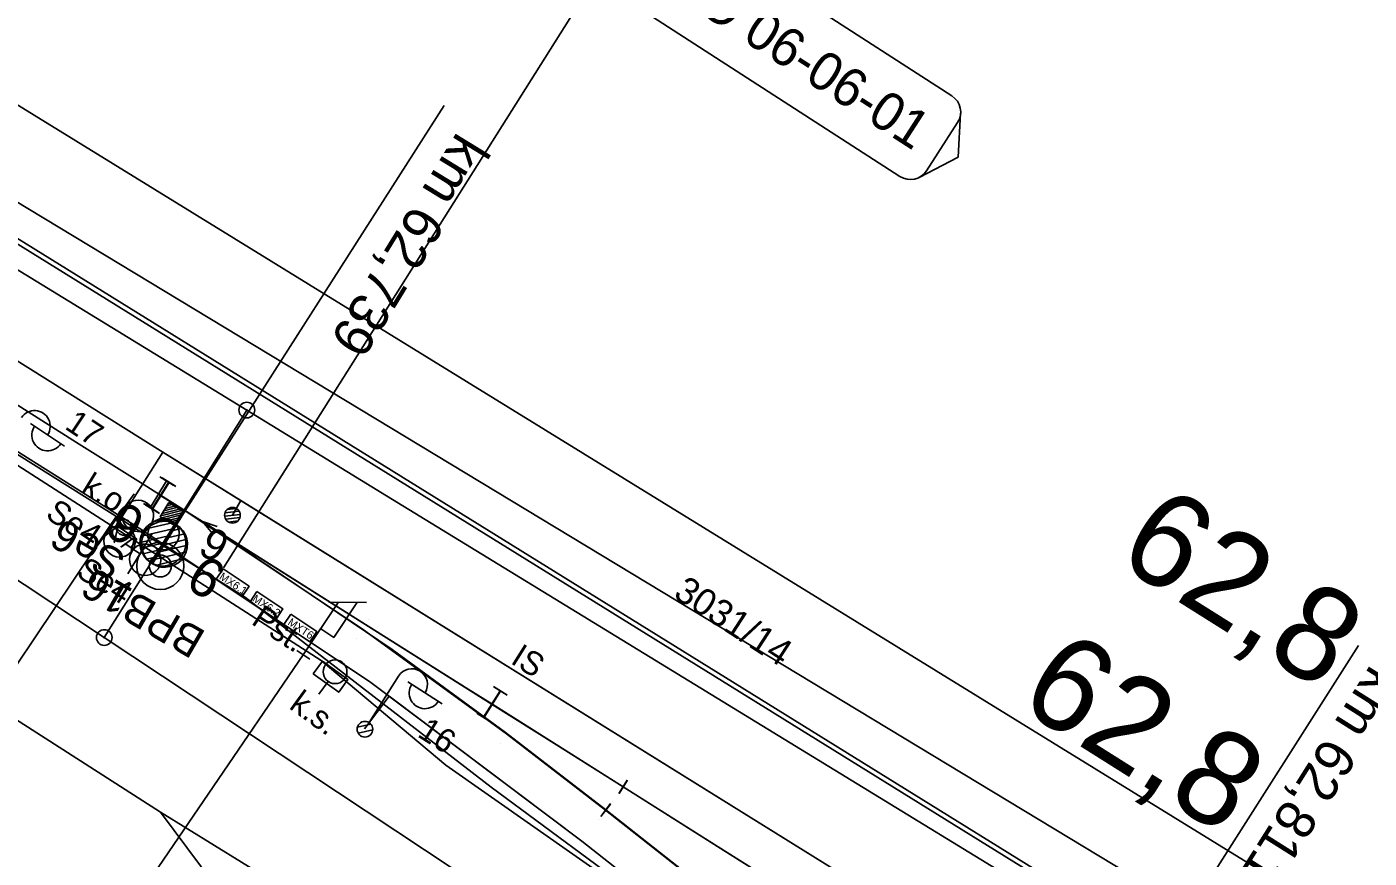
# Model space of a CAD drawing. Extents: x -621168 to -620292, y -1122748 to -1122069.
# Drawn here: x -620861.7 to -620776.3, y -1122349.2 to -1122296.3 of the extents above; entities that cross this region are included whole.
import ezdxf

# ---------------------------------------------------------------- set-up
doc = ezdxf.new("R2010")
doc.units = 0
for name, color, linetype in [('060601_EOV', 7, 'Continuous'), ('060604_ROZVODY_SEE', 7, 'Continuous'), ('bubliny', 7, 'Continuous'), ('CETIN', 7, 'Continuous'), ('HranDP', 7, 'Continuous'), ('Hranice parcel', 7, 'Continuous'), ('Parcelní čísla', 7, 'Continuous'), ('PS 06-14-01_trasa_sdělovací_nové', 7, 'Continuous'), ('SEE', 7, 'Continuous'), ('SSZT', 7, 'Continuous'), ('SSZT-DK', 7, 'Continuous'), ('UZEMNĚNÍ', 7, 'Continuous'), ('Vrstva 1', 7, 'Continuous'), ('Vrstva 10', 7, 'Continuous'), ('Vrstva 2', 7, 'Continuous'), ('Vrstva 25', 7, 'Continuous'), ('Vrstva 27', 7, 'Continuous'), ('Vrstva 3', 7, 'Continuous'), ('Vrstva 36', 7, 'Continuous'), ('Vrstva 6', 7, 'Continuous'), ('Vrstva 62', 7, 'Continuous'), ('Vrstva 7', 7, 'Continuous'), ('Značky bodu BP', 7, 'Continuous'), ('ČD-T', 7, 'Continuous')]:
    doc.layers.add(name, color=color, linetype=linetype)

msp = doc.modelspace()

# ---------------------------------------------------------------- linework, layer by layer
at = {"layer": '060601_EOV'}
msp.add_line((-620846.682, -1122333.419), (-620846.69, -1122333.431), dxfattribs=at)
for points in [[(-620849.226, -1122330.78), (-620847.572, -1122331.882), (-620848.007, -1122332.536), (-620849.661, -1122331.435)], [(-620847.074, -1122332.214), (-620845.42, -1122333.316), (-620845.855, -1122333.97), (-620847.509, -1122332.868)], [(-620844.922, -1122333.647), (-620843.268, -1122334.749), (-620843.703, -1122335.403), (-620845.357, -1122334.302)]]:
    msp.add_lwpolyline(points, close=True, dxfattribs=at)
for points in [[(-620377.179, -1122637.257), (-620411.557, -1122614.916), (-620424.156, -1122607.087), (-620443.525, -1122595.005), (-620456.111, -1122587.123), (-620447.823, -1122572.959), (-620450.948, -1122571.455), (-620470.592, -1122561.479), (-620499.61, -1122545.574), (-620522.038, -1122531.471), (-620538.89, -1122521.208), (-620599.215, -1122483.216), (-620683.524, -1122429.444), (-620729.121, -1122400.659), (-620738.886, -1122415.694), (-620750.529, -1122408.246), (-620763.558, -1122399.82), (-620784.65, -1122386.386), (-620822.218, -1122362.419), (-620817.53, -1122355.085), (-620826.407, -1122348.082), (-620839.916, -1122337.943), (-620848.842, -1122331.997), (-620848.834, -1122331.986)], [(-620844.53, -1122334.853), (-620844.531, -1122334.852), (-620844.539, -1122334.864)]]:
    msp.add_lwpolyline(points, dxfattribs=at)
at = {"layer": '060604_ROZVODY_SEE'}
msp.add_line((-620840.227, -1122340.951), (-620838.671, -1122338.878), dxfattribs=at)
msp.add_lwpolyline([(-620443.525, -1122595.005), (-620456.111, -1122587.123), (-620447.823, -1122572.959), (-620450.948, -1122571.455), (-620470.592, -1122561.479), (-620499.61, -1122545.574), (-620522.038, -1122531.471), (-620538.89, -1122521.208), (-620599.215, -1122483.216), (-620683.524, -1122429.444), (-620729.121, -1122400.659), (-620738.886, -1122415.694), (-620750.529, -1122408.246), (-620763.558, -1122399.82), (-620784.65, -1122386.386), (-620822.218, -1122362.419), (-620817.53, -1122355.085), (-620826.407, -1122348.082), (-620839.916, -1122337.943), (-620854.567, -1122328.184), (-620868.06, -1122319.694), (-620885.37, -1122308.815), (-620912.868, -1122291.527), (-620913.325, -1122292.255)], dxfattribs=at)
at = {"layer": 'bubliny'}
msp.add_line((-620849.204, -1122330.707), (-620823.975, -1122290.686), dxfattribs=at)
for points in [[(-620821.297, -1122288.788), (-620802.862, -1122300.695)], [(-620806.17, -1122305.815), (-620824.604, -1122293.908)], [(-620802.307, -1122301.789), (-620802.468, -1122304.578), (-620804.944, -1122305.872)], [(-620804.484, -1122305.453), (-620802.5, -1122302.38)], [(-620802.5, -1122302.38), (-620804.484, -1122305.453)]]:
    msp.add_lwpolyline(points, dxfattribs=at)
for centre, start, end in [((-620803.524, -1122301.719), 327.14101, 57.14101), ((-620803.524, -1122301.719), 327.14101, 356.69293), ((-620805.508, -1122304.791), 237.14101, 327.14101), ((-620805.508, -1122304.791), 297.58925, 327.14101)]:
    msp.add_arc(centre, 1.219, start, end, dxfattribs=at)
at = {"layer": 'CETIN'}
msp.add_lwpolyline([(-621086.886, -1122186.715), (-621044.703, -1122204.841), (-620975.938, -1122239.692), (-620943.103, -1122258.616), (-620748.436, -1122376.269), (-620484.52, -1122538.147)], dxfattribs=at)
at = {"layer": 'HranDP'}
msp.add_line((-620856.79, -1122335.14), (-620821.12, -1122358.76), dxfattribs=at)
for points in [[(-620847.72, -1122320.67), (-620907.48, -1122284.08), (-620974.87, -1122244.96), (-620982.44, -1122240.65)], [(-620902.62, -1122306.44), (-620882.26, -1122318.28), (-620856.79, -1122335.14)], [(-620847.72, -1122320.67), (-620838.83, -1122326.12), (-620768.63, -1122369.09), (-620748.53, -1122378.52), (-620702.13, -1122406.7), (-620691.02, -1122413.66), (-620638.48, -1122446.57), (-620552.09, -1122499.2)]]:
    msp.add_lwpolyline(points, dxfattribs=at)
at = {"layer": 'Hranice parcel'}
for p, q in [((-620866.03, -1122298.98), (-620688.16, -1122408.5)), ((-620853.22, -1122346.25), (-620894.54, -1122319.77)), ((-620847.72, -1122320.67), (-620856.79, -1122335.14)), ((-620856.79, -1122335.14), (-620821.12, -1122358.76))]:
    msp.add_line(p, q, dxfattribs=at)
for points in [[(-620847.72, -1122320.67), (-620907.48, -1122284.08), (-620974.87, -1122244.96), (-620982.44, -1122240.65)], [(-620902.62, -1122306.44), (-620882.26, -1122318.28), (-620856.79, -1122335.14)], [(-620847.72, -1122320.67), (-620838.83, -1122326.12), (-620768.63, -1122369.09), (-620748.53, -1122378.52), (-620702.13, -1122406.7), (-620691.02, -1122413.66), (-620638.48, -1122446.57), (-620552.09, -1122499.2)], [(-620825.92, -1122365.89), (-620834.44, -1122358.28), (-620836.04, -1122356.85), (-620853.22, -1122346.25)], [(-620853.22, -1122346.25), (-620843.09, -1122359.81), (-620845.8, -1122363.88), (-620848.5, -1122367.99), (-620848.87, -1122368.55)]]:
    msp.add_lwpolyline(points, dxfattribs=at)
at = {"layer": 'PS 06-14-01_trasa_sdělovací_nové'}
msp.add_lwpolyline([(-620756.33, -1122383.523), (-620759.752, -1122381.362), (-620756.353, -1122375.206), (-620764.724, -1122371.2), (-620767.847, -1122376.3), (-620853.066, -1122323.342), (-620895.691, -1122296.632), (-620912.11, -1122286.226), (-620914.885, -1122290.617), (-620964.537, -1122259.534), (-620982.106, -1122249.221), (-620983.24, -1122251.5), (-621017.63, -1122231.729), (-621052.339, -1122216.079), (-621085.519, -1122202.489), (-621084.026, -1122198.756), (-621092.027, -1122195.557)], dxfattribs=at)
at = {"layer": 'SEE'}
msp.add_lwpolyline([(-620377.188, -1122637.273), (-620390.254, -1122629.02), (-620411.934, -1122614.961), (-620423.125, -1122608.012), (-620468.337, -1122579.91), (-620468.337, -1122579.91), (-620460.94, -1122568.103), (-620517.418, -1122533.032), (-620535.001, -1122522.477), (-620545.407, -1122539.454), (-620611.375, -1122497.696), (-620665.569, -1122462.755), (-620686.035, -1122449.829), (-620727.537, -1122423.183), (-620794.508, -1122379.862), (-620815.52, -1122356.954), (-620832.168, -1122344.663), (-620847.808, -1122332.592), (-620908.257, -1122294.686)], dxfattribs=at)
at = {"layer": 'SSZT'}
msp.add_lwpolyline([(-620879.238, -1122313.316), (-620842.993, -1122336.61), (-620835.049, -1122343.251), (-620812.66, -1122358.949), (-620764.902, -1122389.752), (-620688.594, -1122438.969), (-620596.981, -1122496.725), (-620576.744, -1122509.484), (-620506.746, -1122556.123), (-620447.293, -1122593.619), (-620377.761, -1122638.259)], dxfattribs=at)
at = {"layer": 'SSZT-DK'}
msp.add_lwpolyline([(-621084.334, -1122182.327), (-621080.248, -1122184.036), (-621051.504, -1122198.928), (-620999.37, -1122227.003), (-620959.935, -1122250.539), (-620931.349, -1122267.519), (-620900.269, -1122286.467), (-620889.147, -1122293.455), (-620783.743, -1122358.818), (-620712.751, -1122398.176), (-620653.117, -1122435.232), (-620617.363, -1122456.738), (-620574.425, -1122482.604), (-620528.157, -1122511.106), (-620496.311, -1122530.834), (-620515.025, -1122558.813), (-620500.383, -1122568.606), (-620465.393, -1122591.454), (-620452.16, -1122605.021), (-620438.234, -1122615.496), (-620392.309, -1122655.212), (-620389.253, -1122658.022)], dxfattribs=at)
at = {"layer": 'UZEMNĚNÍ'}
msp.add_lwpolyline([(-620742.353, -1122414.851), (-620741.729, -1122413.876), (-620750.529, -1122408.246), (-620763.558, -1122399.82), (-620784.65, -1122386.386), (-620822.218, -1122362.419), (-620817.53, -1122355.085), (-620826.407, -1122348.082), (-620838.671, -1122338.878), (-620840.227, -1122340.951)], dxfattribs=at)
at = {"layer": 'Vrstva 1'}
for p, q in [((-620856.015, -1122328.01), (-620853.066, -1122323.342)), ((-620848.094, -1122326.432), (-620853.066, -1122323.342)), ((-620806.105, -1122352.525), (-620848.094, -1122326.432)), ((-620856.015, -1122328.01), (-620854.725, -1122328.89))]:
    msp.add_line(p, q, dxfattribs=at)
for points in [[(-620853.066, -1122323.342), (-620895.691, -1122296.632), (-620912.11, -1122286.226)], [(-620865.133, -1122318.582), (-620858.377, -1122322.838), (-620854.485, -1122325.283), (-620853.208, -1122326.085), (-620851.733, -1122327.008), (-620850.549, -1122327.758), (-620840.578, -1122334.049), (-620833.632, -1122338.433), (-620832.14, -1122339.366), (-620823.776, -1122344.632), (-620817.743, -1122348.457), (-620811.366, -1122352.452)], [(-620853.345, -1122326.031), (-620853.187, -1122326.13), (-620851.644, -1122327.076), (-620843.142, -1122332.434), (-620837.627, -1122335.918), (-620832.116, -1122339.39), (-620828.016, -1122341.966), (-620823.788, -1122344.633), (-620816.971, -1122348.943), (-620810.355, -1122353.089), (-620803.86, -1122357.181), (-620803.36, -1122357.495), (-620800.131, -1122359.525), (-620798.65, -1122360.458), (-620794.421, -1122363.123), (-620788.102, -1122367.105), (-620781.123, -1122371.499), (-620774.168, -1122375.876)], [(-620848.094, -1122326.432), (-620848.094, -1122326.432), (-620848.634, -1122327.362)], [(-620851.644, -1122327.076), (-620843.142, -1122332.434), (-620837.627, -1122335.918), (-620832.116, -1122339.39), (-620828.016, -1122341.966), (-620823.788, -1122344.633), (-620816.971, -1122348.943), (-620810.355, -1122353.089), (-620803.86, -1122357.181), (-620803.36, -1122357.495), (-620800.131, -1122359.525), (-620798.65, -1122360.458), (-620794.421, -1122363.123), (-620788.102, -1122367.105), (-620781.123, -1122371.499), (-620774.168, -1122375.876), (-620767.514, -1122380.058), (-620763.223, -1122382.761), (-620756.392, -1122387.049), (-620748.87, -1122391.776), (-620741.59, -1122396.353), (-620734.607, -1122400.749), (-620727.792, -1122405.031)], [(-620851.644, -1122327.076), (-620840.376, -1122334.591), (-620831.192, -1122341.263), (-620824.896, -1122346.12), (-620811.348, -1122356.777), (-620800.849, -1122364.554), (-620800.095, -1122365.072), (-620796.174, -1122367.693), (-620795.017, -1122368.443), (-620786.31, -1122373.928), (-620764.415, -1122387.671), (-620747.632, -1122398.188), (-620733.731, -1122406.893), (-620718.349, -1122416.524), (-620703.006, -1122426.145), (-620686.977, -1122436.203), (-620670.849, -1122446.339), (-620652.243, -1122458.025), (-620632.992, -1122470.125), (-620616.992, -1122480.169), (-620599.707, -1122491.044), (-620582.331, -1122501.971), (-620566.971, -1122511.728)], [(-620850.549, -1122327.758), (-620838.472, -1122335.901), (-620831.257, -1122341.177), (-620824.882, -1122346.101), (-620819.561, -1122350.304), (-620813.61, -1122354.966)], [(-620854.725, -1122328.89), (-620855.091, -1122329.442), (-620854.511, -1122329.81)]]:
    msp.add_lwpolyline(points, dxfattribs=at)
at = {"layer": 'Vrstva 10'}
for p, q in [((-620841.912, -1122332.916), (-620844.131, -1122336.244)), ((-620842.494, -1122332.888), (-620840.109, -1122332.917)), ((-620844.547, -1122335.967), (-620843.715, -1122336.521)), ((-620844.131, -1122336.244), (-620860.567, -1122360.289))]:
    msp.add_line(p, q, dxfattribs=at)
msp.add_lwpolyline([(-620840.719, -1122332.93), (-620842.189, -1122335.135), (-620843.021, -1122334.58)], dxfattribs=at)
at = {"layer": 'Vrstva 2'}
for p, q in [((-620851.644, -1122327.076), (-620835.166, -1122301.296)), ((-620852.912, -1122326.928), (-620852.321, -1122326.781)), ((-620852.816, -1122326.769), (-620852.48, -1122326.685)), ((-620852.72, -1122326.61), (-620852.639, -1122326.589)), ((-620853.199, -1122327.404), (-620851.844, -1122327.069)), ((-620853.127, -1122327.521), (-620851.854, -1122327.206)), ((-620853.103, -1122327.245), (-620852.003, -1122326.973)), ((-620853.008, -1122327.086), (-620852.162, -1122326.877)), ((-620852.967, -1122327.617), (-620851.95, -1122327.365)), ((-620852.809, -1122327.713), (-620852.046, -1122327.524)), ((-620852.65, -1122327.809), (-620852.141, -1122327.683)), ((-620852.276, -1122327.881), (-620851.733, -1122327.008)), ((-620852.187, -1122327.962), (-620851.644, -1122327.076)), ((-620848.138, -1122327.306), (-620849.129, -1122327.418)), ((-620848.203, -1122327.112), (-620849.111, -1122327.214)), ((-620848.159, -1122327.51), (-620849.065, -1122327.612)), ((-620848.383, -1122326.931), (-620848.975, -1122326.998)), ((-620853.736, -1122328.526), (-620855.286, -1122331.095)), ((-620852.502, -1122328.242), (-620854.449, -1122328.69)), ((-620852.376, -1122327.829), (-620854.227, -1122328.254)), ((-620852.276, -1122327.882), (-620853.83, -1122330.363)), ((-620852.187, -1122327.962), (-620853.717, -1122330.457)), ((-620851.655, -1122328.533), (-620852.685, -1122328.78)), ((-620852.491, -1122327.905), (-620852.237, -1122327.842)), ((-620851.895, -1122328.199), (-620852.404, -1122328.321)), ((-620852.277, -1122327.881), (-620852.276, -1122327.882)), ((-620848.294, -1122327.726), (-620848.884, -1122327.793)), ((-620852.783, -1122328.691), (-620854.514, -1122329.09)), ((-620853.065, -1122329.141), (-620854.473, -1122329.465)), ((-620851.49, -1122329.274), (-620853.248, -1122329.696)), ((-620851.525, -1122328.892), (-620852.967, -1122329.237)), ((-620853.347, -1122329.59), (-620854.336, -1122329.818)), ((-620853.628, -1122330.04), (-620854.093, -1122330.147)), ((-620851.817, -1122330.135), (-620853.539, -1122330.548)), ((-620851.568, -1122329.684), (-620853.529, -1122330.154)), ((-620824.055, -1122345.056), (-620823.521, -1122344.21)), ((-620823.51, -1122344.209), (-620824.042, -1122345.055)), ((-620825.205, -1122346.513), (-620824.587, -1122345.727)), ((-620824.576, -1122345.705), (-620825.188, -1122346.497))]:
    msp.add_line(p, q, dxfattribs=at)
msp.add_lwpolyline([(-620852.69, -1122326.559), (-620851.79, -1122327.101), (-620852.333, -1122328), (-620853.232, -1122327.458)], close=True, dxfattribs=at)
msp.add_lwpolyline([(-620852.69, -1122326.559), (-620851.79, -1122327.101), (-620852.333, -1122328), (-620853.232, -1122327.458)], close=True, dxfattribs=at)
for points in [[(-620851.644, -1122327.076), (-620837.627, -1122335.918), (-620832.116, -1122339.39), (-620828.016, -1122341.966), (-620823.788, -1122344.633)], [(-620851.644, -1122327.076), (-620840.376, -1122334.591), (-620831.192, -1122341.263), (-620824.896, -1122346.12)], [(-620849.603, -1122328.083), (-620850.549, -1122327.758), (-620849.893, -1122328.513)]]:
    msp.add_lwpolyline(points, dxfattribs=at)
for centre, radius in [((-620853.059, -1122329.128), 1.462), ((-620848.634, -1122327.362), 0.5), ((-620853.226, -1122330.585), 1.5), ((-620853.226, -1122330.585), 0.7)]:
    msp.add_circle(centre, radius, dxfattribs=at)
for centre, radius, start, end in [((-620853.053, -1122329.122), 1.464, 57.98278, 237.94363), ((-620852.957, -1122329.206), 1.463, 58.25314, 238.72266), ((-620852.952, -1122329.209), 1.463, 238.50747, 58.46832)]:
    msp.add_arc(centre, radius, start, end, dxfattribs=at)
at = {"layer": 'Vrstva 25'}
for p, q in [((-620861.473, -1122321.535), (-620859.31, -1122322.977)), ((-620839.94, -1122340.549), (-620838.075, -1122337.588)), ((-620837.483, -1122337.961), (-620835.283, -1122339.347)), ((-620840.689, -1122340.841), (-620839.831, -1122340.646)), ((-620840.642, -1122341.214), (-620839.708, -1122341.002))]:
    msp.add_line(p, q, dxfattribs=at)
msp.add_circle((-620840.207, -1122340.972), 0.5, dxfattribs=at)
for centre, start, end in [((-620861.224, -1122321.701), 326.29937, 146.29937), ((-620860.398, -1122322.266), 145.5968, 327.00195), ((-620837.229, -1122338.121), 327.78855, 147.78855), ((-620836.389, -1122338.664), 147.08598, 328.49112)]:
    msp.add_arc(centre, 1, start, end, dxfattribs=at)
at = {"layer": 'Vrstva 27'}
msp.add_line((-620855.576, -1122328.105), (-620855.49, -1122328.157), dxfattribs=at)
msp.add_circle((-620855.533, -1122328.131), 0.5, dxfattribs=at)
at = {"layer": 'Vrstva 3'}
for p, q in [((-620852.396, -1122325.44), (-620853.249, -1122324.917)), ((-620853.1, -1122324.972), (-620852.253, -1122325.504)), ((-620852.238, -1122325.539), (-620853.091, -1122325.016)), ((-620853.868, -1122326.884), (-620852.822, -1122325.178)), ((-620852.676, -1122325.238), (-620853.74, -1122326.932)), ((-620853.71, -1122326.983), (-620852.664, -1122325.277)), ((-620853.441, -1122327.145), (-620854.294, -1122326.622)), ((-620854.163, -1122326.666), (-620853.316, -1122327.198)), ((-620853.283, -1122327.244), (-620854.136, -1122326.721)), ((-620831.607, -1122338.52), (-620832.673, -1122340.212)), ((-620831.584, -1122338.543), (-620832.648, -1122340.237)), ((-620831.584, -1122338.543), (-620832.648, -1122340.237)), ((-620832.03, -1122338.253), (-620831.184, -1122338.786)), ((-620832.007, -1122338.277), (-620831.161, -1122338.809)), ((-620832.007, -1122338.277), (-620831.161, -1122338.809)), ((-620833.096, -1122339.946), (-620832.25, -1122340.479)), ((-620833.071, -1122339.971), (-620832.225, -1122340.503)), ((-620833.071, -1122339.971), (-620832.225, -1122340.503))]:
    msp.add_line(p, q, dxfattribs=at)
at = {"layer": 'Vrstva 36'}
msp.add_line((-620842.553, -1122337.928), (-620843.141, -1122338.737), dxfattribs=at)
msp.add_lwpolyline([(-620843.49, -1122337.448), (-620842.902, -1122336.639), (-620841.284, -1122337.814), (-620841.872, -1122338.623), (-620843.49, -1122337.448)], dxfattribs=at)
msp.add_circle((-620842.108, -1122337.316), 0.757, dxfattribs=at)
at = {"layer": 'Vrstva 6'}
for p, q in [((-620854.879, -1122326.004), (-620856.043, -1122327.63)), ((-620856.043, -1122327.63), (-620857.207, -1122329.256)), ((-620856.572, -1122328.245), (-620856.018, -1122327.413)), ((-620856.295, -1122327.829), (-620873.179, -1122352.97)), ((-620792.925, -1122360.656), (-620777.003, -1122335.648))]:
    msp.add_line(p, q, dxfattribs=at)
for centre in [(-620854.648, -1122327.4), (-620853.02, -1122328.564), (-620855.812, -1122329.026), (-620854.184, -1122330.191)]:
    msp.add_ellipse(centre, major_axis=(0.814, -0.582), ratio=0.999505, dxfattribs=at)
at = {"layer": 'Vrstva 62'}
for p, q in [((-620852.963, -1122325.419), (-620852.963, -1122325.419)), ((-620852.803, -1122325.519), (-620852.803, -1122325.519)), ((-620853.727, -1122326.643), (-620853.727, -1122326.643)), ((-620853.571, -1122326.741), (-620853.571, -1122326.741)), ((-620851.254, -1122326.485), (-620851.254, -1122326.485)), ((-620852.144, -1122327.639), (-620852.144, -1122327.639)), ((-620839.987, -1122333.983), (-620839.987, -1122333.983)), ((-620840.766, -1122335.2), (-620840.766, -1122335.2)), ((-620830.79, -1122340.66), (-620830.79, -1122340.66)), ((-620831.595, -1122341.865), (-620831.595, -1122341.865)), ((-620824.451, -1122345.545), (-620824.451, -1122345.545)), ((-620825.342, -1122346.695), (-620825.342, -1122346.695))]:
    msp.add_line(p, q, dxfattribs=at)
at = {"layer": 'Značky bodu BP'}
for centre, radius in [((-620847.72, -1122320.67), 0.5), ((-620847.72, -1122320.67), 0.0303), ((-620856.79, -1122335.14), 0.5), ((-620856.79, -1122335.14), 0.0303)]:
    msp.add_circle(centre, radius, dxfattribs=at)
at = {"layer": 'ČD-T'}
msp.add_lwpolyline([(-621084.188, -1122182.075), (-621080.06, -1122183.802), (-621051.317, -1122198.693), (-620999.183, -1122226.768), (-620959.747, -1122250.305), (-620931.162, -1122267.284), (-620900.082, -1122286.233), (-620888.96, -1122293.22), (-620783.556, -1122358.583), (-620712.564, -1122397.941), (-620652.93, -1122434.998), (-620617.176, -1122456.504), (-620574.237, -1122482.37), (-620527.969, -1122510.872), (-620481.077, -1122540.08), (-620497.003, -1122565.384), (-620499.265, -1122568.979), (-620465.206, -1122591.22), (-620451.973, -1122604.786), (-620438.046, -1122615.261), (-620392.122, -1122654.977), (-620389.098, -1122657.757)], dxfattribs=at)

# ---------------------------------------------------------------- texts
at = {"layer": '060601_EOV'}
for s, p in [('MX6.1', (-620849.519, -1122331.383)), ('MX6.2', (-620847.41, -1122332.788)), ('MXT6', (-620845.16, -1122334.287))]:
    msp.add_text(s, height=0.5, rotation=326.33147, dxfattribs=at).set_placement(p)
at = {"layer": 'bubliny'}
msp.add_text('SO 06-06-01', height=2.4384, rotation=327.14101, dxfattribs=at).set_placement((-620820.996, -1122294.062))
at = {"layer": 'Parcelní čísla'}
msp.add_text('3031/14', height=1.7, rotation=327, dxfattribs=at).set_placement((-620820.66, -1122332.557))
at = {"layer": 'Vrstva 10'}
msp.add_text('Pst.', height=1.5, rotation=326.29937, dxfattribs=at).set_placement((-620847.503, -1122334.238))
at = {"layer": 'Vrstva 2'}
for s, rotation, p in [('km 62,739', 238.4879, (-620834.319, -1122302.904)), ('6', 147.9632, (-620853.991, -1122327.354)), ('6', 328.4879, (-620851.746, -1122331.884))]:
    msp.add_text(s, height=2.5, rotation=rotation, dxfattribs=at).set_placement(p)
at = {"layer": 'Vrstva 25'}
for s, rotation, p in [('17', 326.29937, (-620859.369, -1122321.818)), ('16', 327.78855, (-620836.935, -1122341.399))]:
    msp.add_text(s, height=1.5, rotation=rotation, dxfattribs=at).set_placement(p)
at = {"layer": 'Vrstva 27'}
msp.add_text('k.o.', height=1.5, rotation=328.4879, dxfattribs=at).set_placement((-620858.344, -1122325.858))
at = {"layer": 'Vrstva 3'}
for s, height, rotation, p in [('Se6', 2, 149.82357, (-620855.284, -1122329.884)), ('6', 2, 149.82357, (-620848.638, -1122328.752)), ('BPB16', 2, 149.82357, (-620850.231, -1122334.814)), ('IS', 1.5, 327.85915, (-620831.011, -1122336.738))]:
    msp.add_text(s, height=height, rotation=rotation, dxfattribs=at).set_placement(p)
at = {"layer": 'Vrstva 36'}
msp.add_text('k.s.', height=1.5, rotation=324.00231, dxfattribs=at).set_placement((-620845.096, -1122339.607))
at = {"layer": 'Vrstva 6'}
for s, height, rotation, p in [('Se4', 1.5, 326.29937, (-620860.603, -1122327.481)), ('A A ', 1, 326.29937, (-620856.85, -1122328.661)), ('Se4', 1.5, 327.86248, (-620858.655, -1122331.199)), ('km 62,811', 2.5, 237.78239, (-620776.215, -1122336.799))]:
    msp.add_text(s, height=height, rotation=rotation, dxfattribs=at).set_placement(p)
at = {"layer": 'Vrstva 7'}
for rotation, p in [(327.84334, (-620792.544, -1122330.295)), (327.78813, (-620798.799, -1122339.471))]:
    msp.add_text('62,8', height=6, rotation=rotation, dxfattribs=at).set_placement(p)

doc.saveas('drawing.dxf')
